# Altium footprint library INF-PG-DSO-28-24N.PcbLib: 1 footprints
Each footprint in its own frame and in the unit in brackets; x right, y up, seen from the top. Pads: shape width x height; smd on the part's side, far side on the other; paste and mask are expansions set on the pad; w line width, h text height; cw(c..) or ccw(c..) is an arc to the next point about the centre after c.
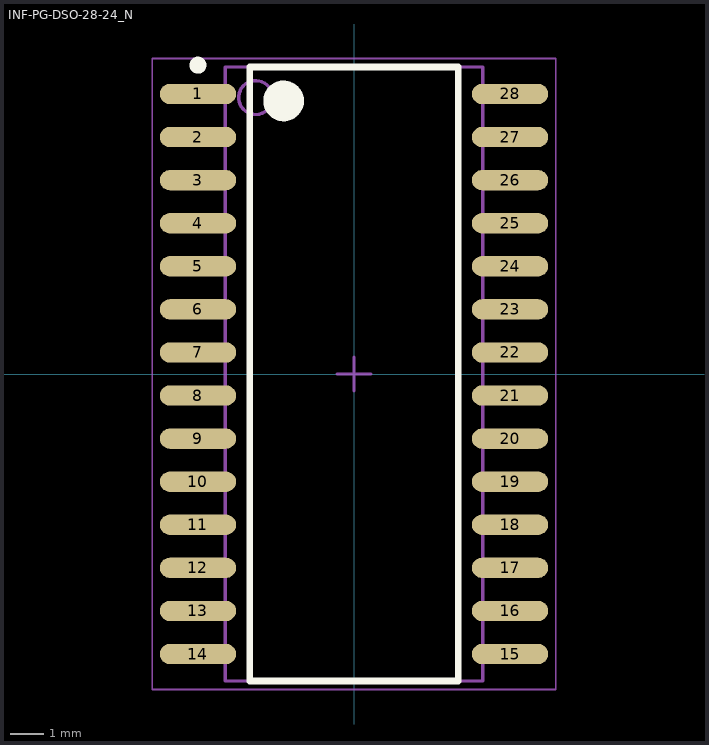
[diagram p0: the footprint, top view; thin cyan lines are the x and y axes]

## INF-PG-DSO-28-24_N [mm] "SOP, 28-Leads, Body 17.9x7.5mm, Pitch 1.27mm, IPC Medium Density"
height 2.65
pads (28):
  oval 2.25x0.6 smd: 1(-4.6,8.255) 2(-4.6,6.985) 3(-4.6,5.715) 4(-4.6,4.445) 5(-4.6,3.175) 6(-4.6,1.905) 7(-4.6,0.635) 8(-4.6,-0.635) 9(-4.6,-1.905) 10(-4.6,-3.175) 11(-4.6,-4.445) 12(-4.6,-5.715) 13(-4.6,-6.985) 14(-4.6,-8.255) 15(4.6,-8.255) 16(4.6,-6.985) 17(4.6,-5.715) 18(4.6,-4.445) 19(4.6,-3.175) 20(4.6,-1.905) 21(4.6,-0.635) 22(4.6,0.635) 23(4.6,1.905) 24(4.6,3.175) 25(4.6,4.445) 26(4.6,5.715) 27(4.6,6.985) 28(4.6,8.255)
Top Overlay:
  circle w0.25: c-4.6,9.105 r0.125
  circle w0.6: c-2.075,8.05 r0.3
  lines w0.2: -3.075,-9.05 -3.075,9.05 3.075,9.05 3.075,-9.05 -3.075,-9.05
Mechanical 13:
  circle w0.1: c-2.9,8.15 r0.5
  lines w0.1: -3.8,-9.05 -3.8,9.05 3.8,9.05 3.8,-9.05 -3.8,-9.05
Mechanical 15:
  lines w0.05: -5.95,-9.3 -5.95,9.3 5.95,9.3 5.95,-9.3 -5.95,-9.3
  lines w0.1: -0.5,0 0.5,0 ; 0,-0.5 0,0.5
3D body: height 2.65, standoff 0.1, extent -3.8,-9.05 3.8,9.05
